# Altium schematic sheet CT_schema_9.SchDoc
size 287 x 160 mm
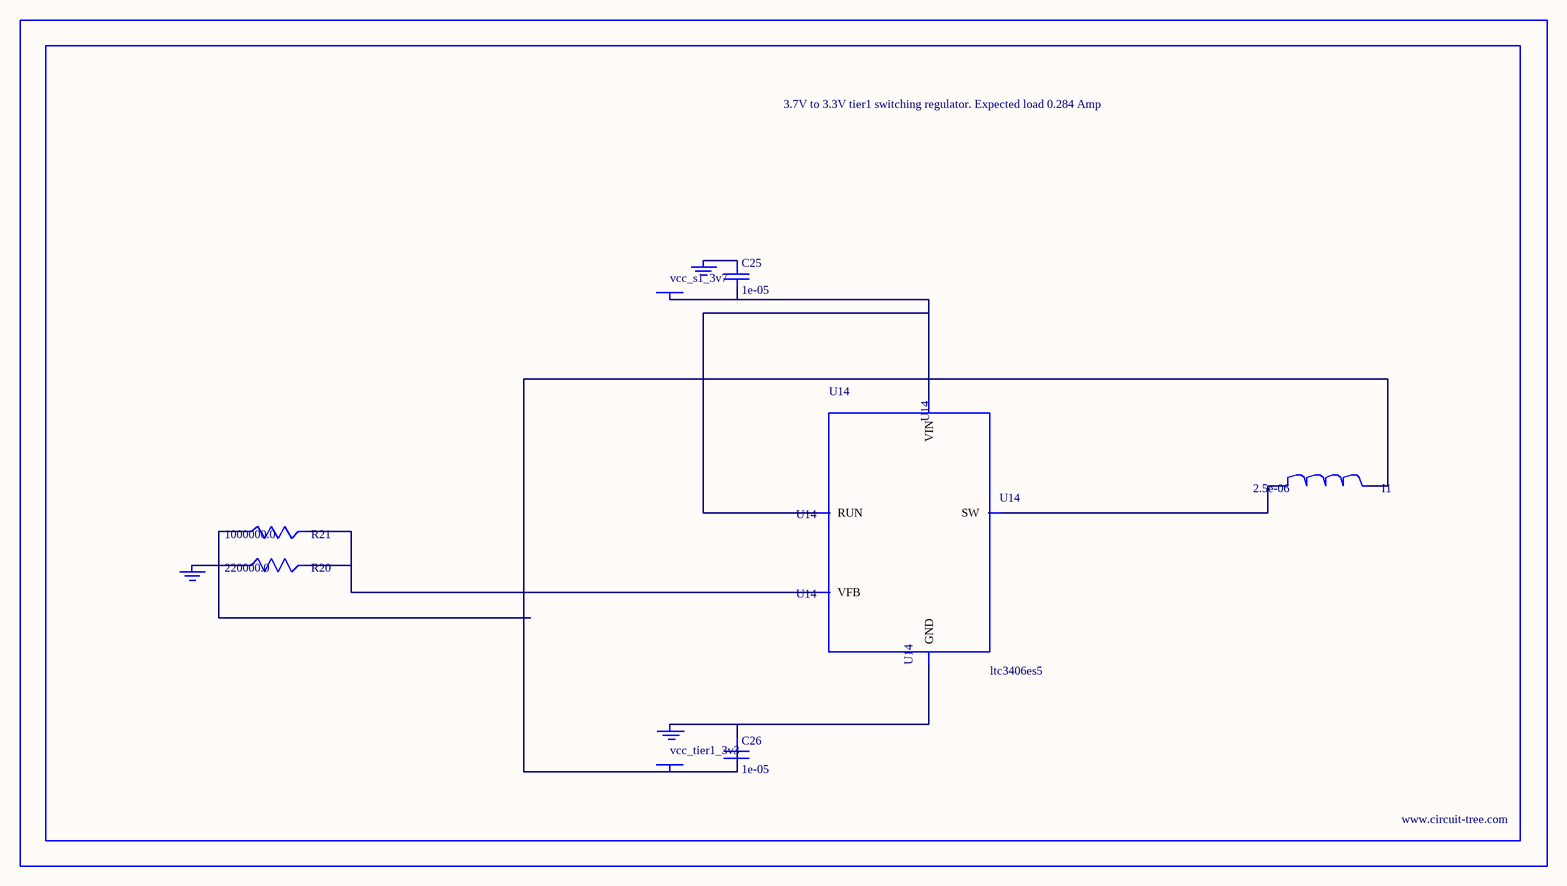
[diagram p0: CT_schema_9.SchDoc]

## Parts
BORDER8  (no value)
C25  1e-05  [C0805]
C26  1e-05  [C0805]
GND_INSTANCE_8_0  (no value)
GND_INSTANCE_8_1  (no value)
GND_INSTANCE_8_2  (no value)
I1  2.5e-06  [DR1040]
POWER_INSTANCE_8_0  vcc_tier1_3v3
POWER_INSTANCE_8_1  vcc_s1_3v7
R20  220000.0  [R0603]
R21  1000000.0  [R0603]
U14  ltc3406es5  [TSOT-23-5]

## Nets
NetC25_1: C25.1 GND_INSTANCE_8_1.0(GND)
NetC25_2: C25.2 POWER_INSTANCE_8_1.0(PWR) U14.1(RUN) U14.4(VIN)
NetC26_1: C26.1 GND_INSTANCE_8_0.0(GND) U14.2(GND)
NetC26_2: C26.2 I1.2 POWER_INSTANCE_8_0.0(PWR) R21.1
NetGND_INSTANCE_8_2_0: GND_INSTANCE_8_2.0(GND) R20.1
NetI1_1: I1.1 U14.3(SW)
NetR20_2: R20.2 R21.2 U14.5(VFB)

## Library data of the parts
BORDER8 = BORDER_PAGE8
C25 C26 = C0805C106K8RACTU
GND_INSTANCE_8_0-GND_INSTANCE_8_2 = GND
I1 = DR1040-2R5-R
POWER_INSTANCE_8_0 POWER_INSTANCE_8_1 = PWR
R20 = RC0603JR-07220KL
R21 = RC0603JR-071ML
